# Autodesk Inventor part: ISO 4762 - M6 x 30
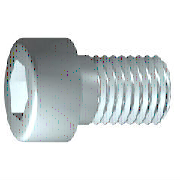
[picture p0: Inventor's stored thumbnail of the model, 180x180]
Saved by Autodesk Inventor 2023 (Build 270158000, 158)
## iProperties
Created: 2015-02
Part Number: ISO 4762 - M6 x 30
Material: Stainless Steel, 440C
Description: Hexagon Socket Head Cap Screw
Document SubType Name: Modeling
Standard: ISO 4762
Designer: Cadskolen
Standard Revision: Fourth edition 2004-03-01
Standards Organization: ISO
Language: en-US
Size Designation: M6 x 30
Categories: <MemberInstance><Categories><Category DisplayName="Fasteners" InternalName="e4da775c-781d-43d5-af7c-5136215cf5a6" Mnemonic="FSTN"><Category DisplayName="Bolts"
Density: 7.75 g/cm^3
Appearance: Semi-Polished
IsCustomPart: 0
Author: Cadskolen
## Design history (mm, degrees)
sketch "Sketch1"
  geometry: L1 (-1.333, 0)-(30, 0); L2 (30, 0)-(30, 3); L3 (30, 3)-(2.5, 3); L4 (2.5, 3)-(1.886, 3); L5 (1.886, 3)-(0, 3); L6 (0, 3)-(0, 5); L7 (0, 5)-(-6, 5); L8 (-6, 5)-(-6, 2.887); L9 (-6, 2.887)-(-3, 2.887); L10 (-3, 2.887)-(-1.333, 0); L11 (-13.2, 0)-(37.2, 0) reference; L12 (0, -1)-(0, 6) reference; L13 (2.5, 3)-(0, 3)
  constraints: 22 end point, 6 parallel, 2 collinear, 2 perpendicular, 1 horizontal, 1 point on line
  dimensions: "d1" = 27.5 distance from line of L3.end L2 (= GEL); "d2" = 0.61355 distance of L4.end L3.end (computed from GAL); "d3" = 6 distance between parallel lines of L8 L6 (= KOH); "d4" = 3 distance of L8.end L9.end (= INTI); "d5" = 60 deg angle of L10 L1; "d6" = 6 diameter of L3 L1 (= GD); "d7" = 6 diameter of L5 L1 (= BDM); "d8" = 5.7735 diameter of L9 L1 (= 1.1547 x SW); "d9" = 10 diameter of L7 L1 (= KOD); "d26" = 30 distance between parallel lines of L12 L2 (= NLG)
revolve "Body" sketch "Sketch1" stored, may be unused: angle "d10" = 90 deg
sketch "Sketch2"
  geometry: L1 (0, -7)-(0, 7) reference; L2 (-7, 0)-(7, 0) reference; L3 (2.887, 0)-(1.443, -2.5); L4 (1.443, -2.5)-(-1.443, -2.5); L5 (-1.443, -2.5)-(-2.887, 0); L6 (-2.887, 0)-(-1.443, 2.5); L7 (-1.443, 2.5)-(1.443, 2.5); L8 (1.443, 2.5)-(2.887, 0); 2 further points
  constraints: 12 end point, 1 coincident, 1 horizontal alignment, 1 point on line, 12 other
extrude "Slot" join sketch "Sketch2" stored distance "d11" = 10; taper "d12" = 0 deg
workplane "Work Plane1"
fillet "Fillet2" dims "d30" = 0.1 (= R)
body "Solid1"
fillet "Fillet1" dims "d17" = 0.6 (= RR)
feature "Thread" dims "d13" = 27.5 (= GEL), "d14" = 0
chamfer "Chamfer1" distance "d15" = 0.61345 (= -0.5 x SPD + 0.5 x GD); stored, may be unused: second distance "d16" = 0.61345 (= GUL), angle "d27" = 45 deg
other parameters: "GD" = 6 [user parameter; used in 2 equation terms], "NLG" = 30 [user parameter; used in 1 equation term], "GEL" = 27.5 [user parameter; used in 2 equation terms], "KOD" = 10 [user parameter; used in 1 equation term], "KOH" = 6 [user parameter; used in 1 equation term], "INTI" = 3 [user parameter; used in 1 equation term], "GAL" = 0.61345 (= 0.61345 x PTC) [user parameter; used in 1 equation term], "GUL" = 0.61345 (= 0.61345 x PTC) [user parameter; used in 1 equation term], "BDM" = 6 (= NND) [user parameter; used in 1 equation term], "SW" = 5 [user parameter; used in 2 equation terms], "RR" = 0.6 [user parameter; used in 1 equation term], "SPD" = 4.7731 (= NND - 1.2269 x PTC) [user parameter; used in 1 equation term], "d19" = 0, "d28" = 0, "d29" = 0, "R" = 0.1 [user parameter; used in 1 equation term], "TOA" = 30 deg [user parameter], "GD1" = 4.7731 (= THREADDIA - 1.2269 x PTC) [user parameter], "THREADDIA" = 6 [user parameter; used in 1 equation term], "FAWI" = 45 deg [user parameter], "PTC" = 1 [user parameter; used in 5 equation terms], "NND" = 6 [user parameter; used in 2 equation terms], "E0" = 5.775 (= 1.155 x SW) [user parameter]
